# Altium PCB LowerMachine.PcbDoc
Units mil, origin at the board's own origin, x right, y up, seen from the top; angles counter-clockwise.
Board outline 1968.5 x 1968.5 mil, 2 copper layers (Top Layer, Bottom Layer); 45 components, 60 nets, 205 pads, 58 vias.
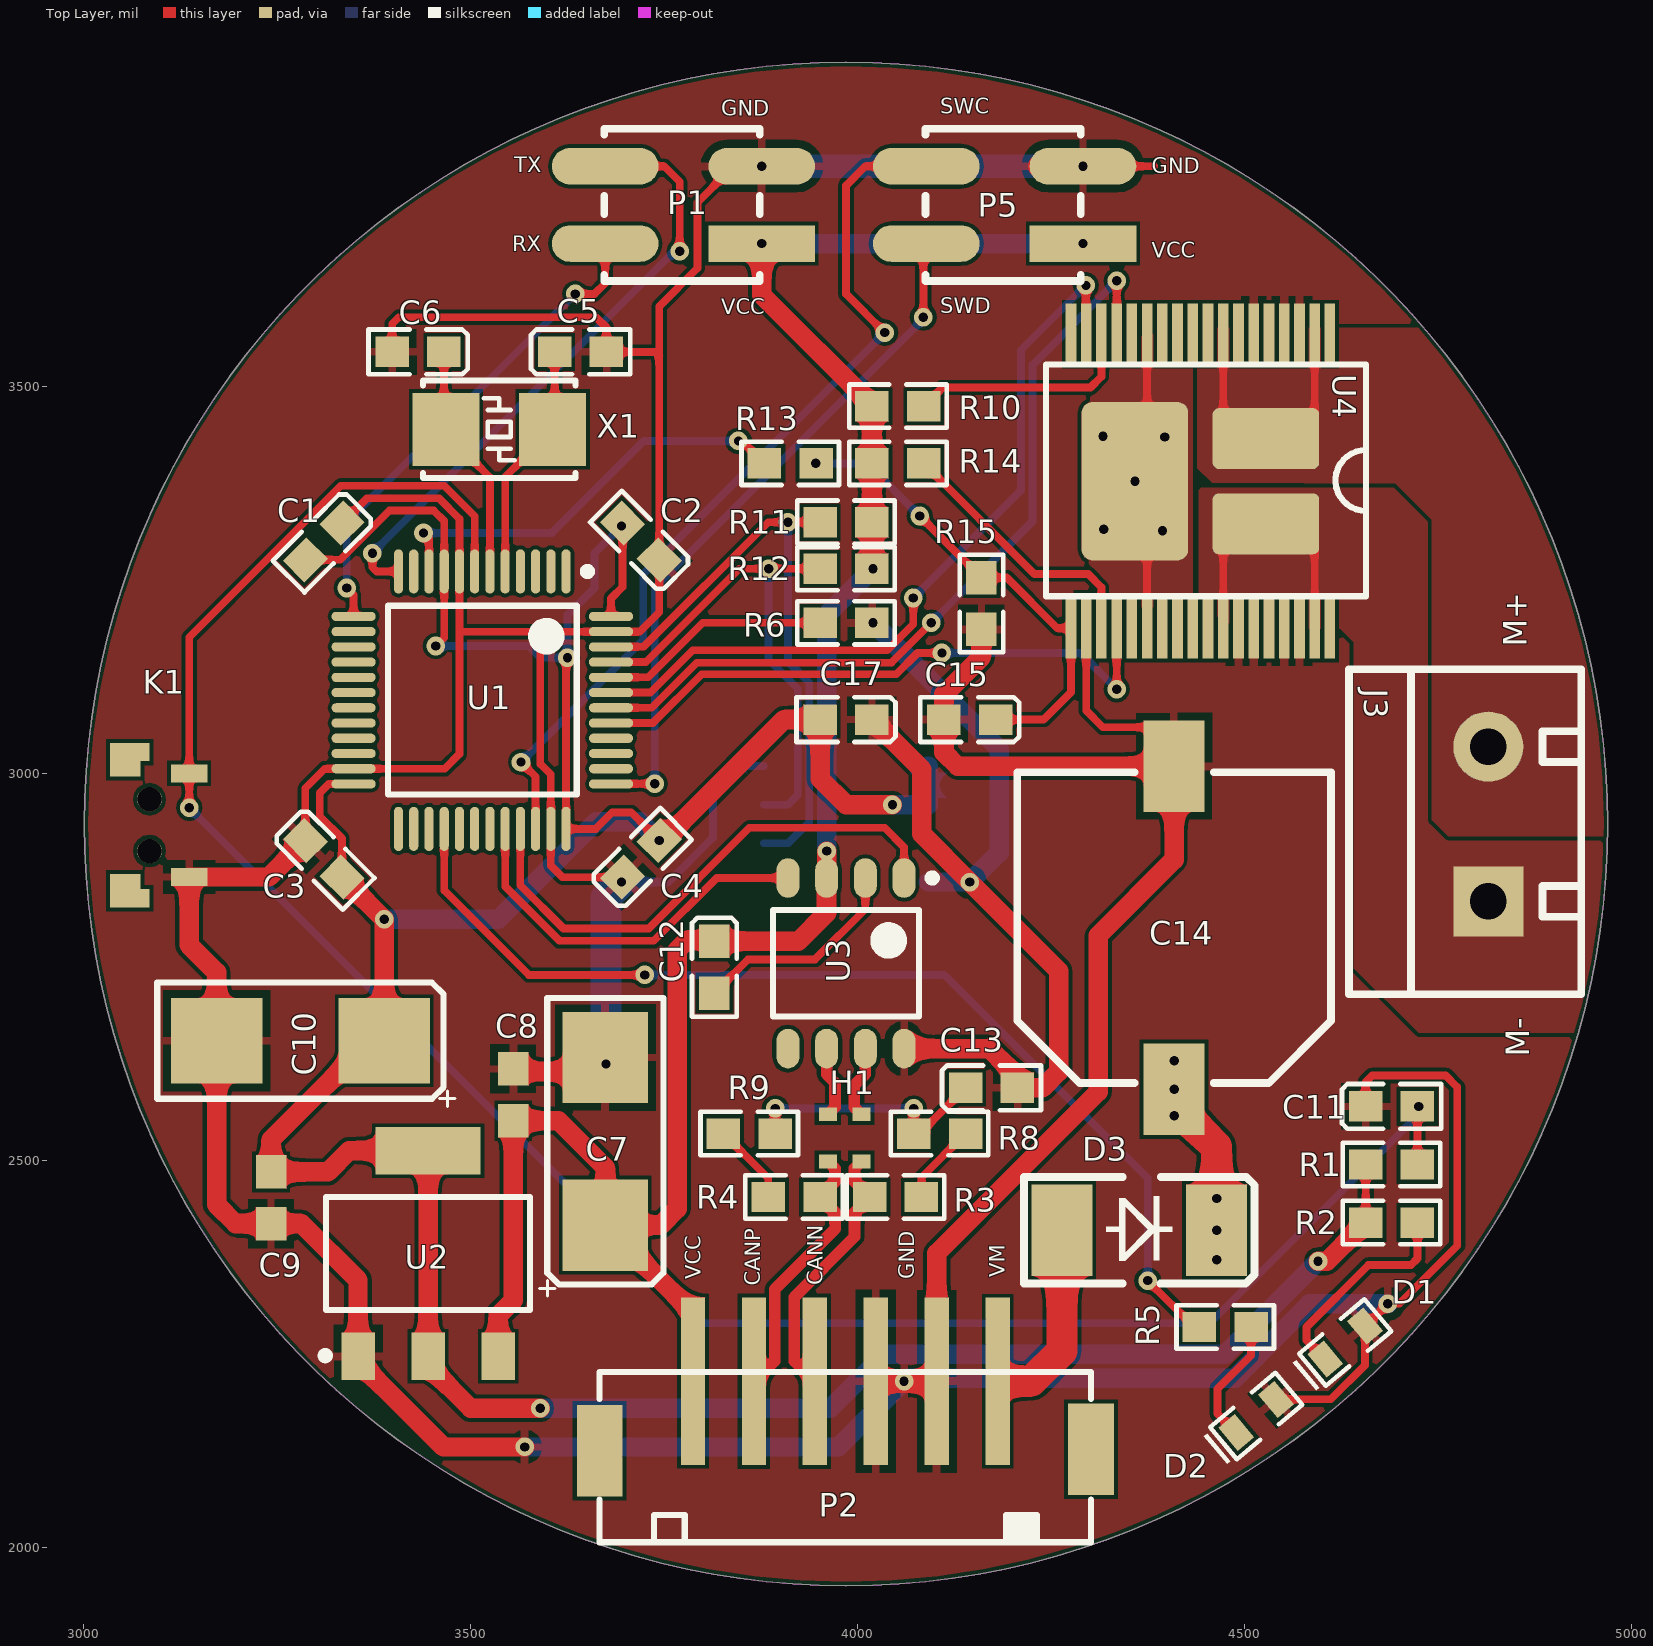
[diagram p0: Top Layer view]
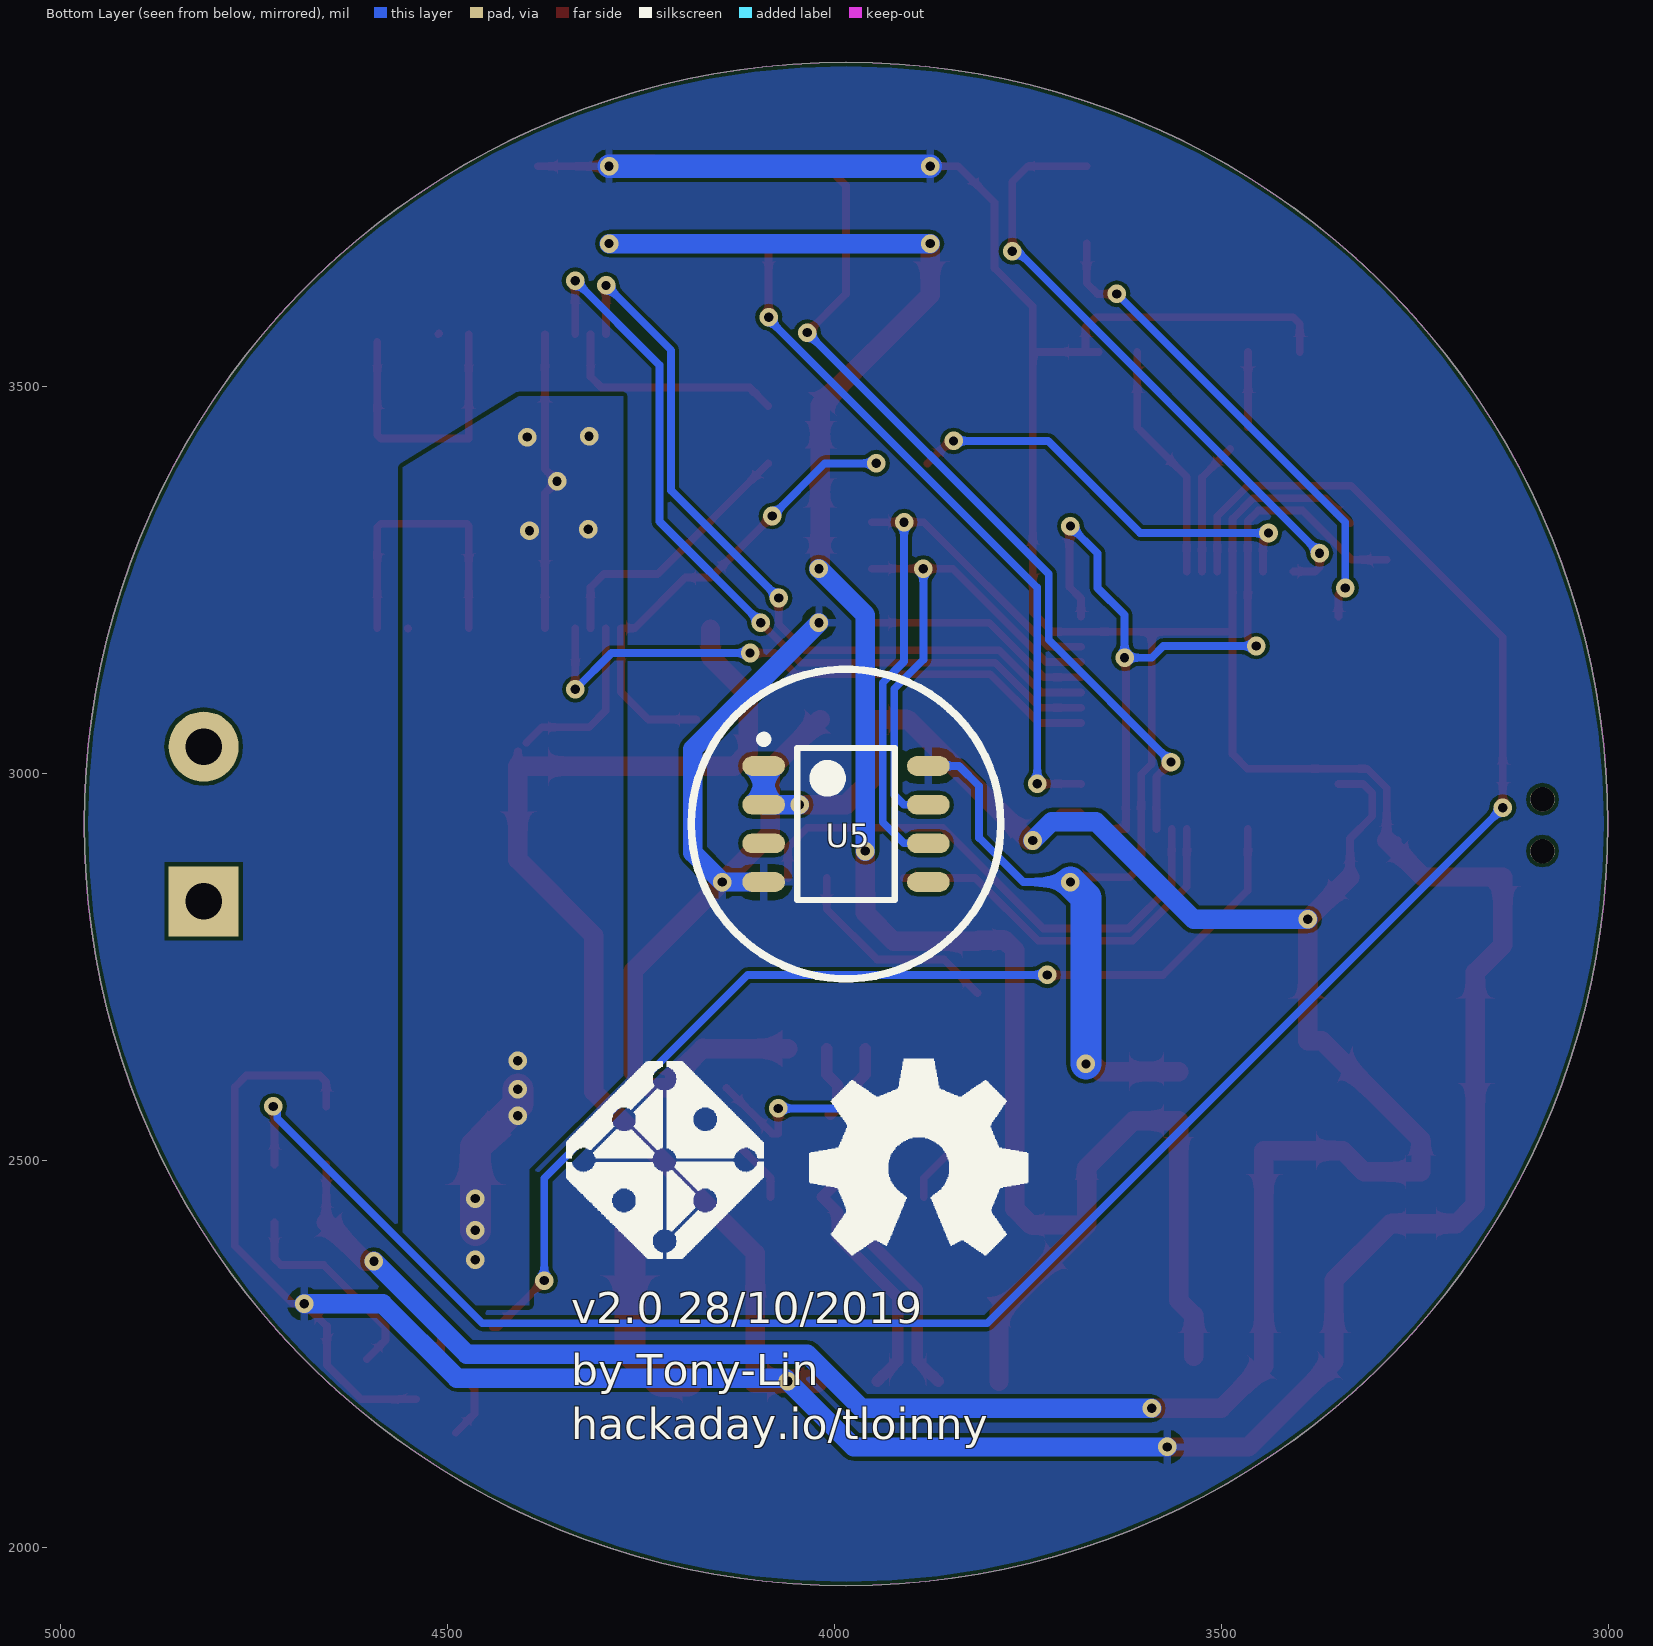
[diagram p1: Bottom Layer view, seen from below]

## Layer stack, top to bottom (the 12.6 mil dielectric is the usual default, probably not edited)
Top Solder: solder mask 0.4, Solder Resist, Dk 3.5
Top Layer: signal copper 1.4
Dielectric 1: dielectric 12.6, FR-4, Dk 4.8
Bottom Layer: signal copper 1.4
Bottom Solder: solder mask 0.4, Solder Resist, Dk 3.5

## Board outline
3000.75,2935 ccw(c3985,2935) 3985,1950.75 ccw(c3985,2935) 4969.25,2935 ccw(c3985,2935) 3985,3919.25 ccw(c3985,2935)

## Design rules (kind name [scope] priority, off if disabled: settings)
Clearance [All] p1: gap=5
DiffPairsRouting [All] p1: maxlimit=10 minlimit=10 mostfreqgap=10 toplayer_minwidth=15 toplayer_maxwidth=15 toplayer_prefwidth=15 bottomlayer_minwidth=15 bottomlayer_maxwidth=15 bottomlayer_prefwidth=15 maxuncoupledlength=500
PolygonConnect PolygonConnect_3 [InNet('24V')] p1: connectstyle=Direct reliefconductorwidth=10 reliefentries=4 polygonreliefangle="90 Angle" airgapwidth=10
PolygonConnect PolygonConnect_2 [InNet('GND')] p2: connectstyle=Relief reliefconductorwidth=10 reliefentries=4 polygonreliefangle="90 Angle" airgapwidth=10
PolygonConnect PolygonConnect_1 [InNet('M+')] p3: connectstyle=Direct reliefconductorwidth=10 reliefentries=4 polygonreliefangle="90 Angle" airgapwidth=10
PolygonConnect [InNet('M-')] p4: connectstyle=Direct reliefconductorwidth=10 reliefentries=4 polygonreliefangle="90 Angle" airgapwidth=10
RoutingVias [All] p1: holewidth=28 width=50 viastyle="Through Hole" minholewidth=28 minwidth=50 maxholewidth=28 maxwidth=50
SolderMaskExpansion [All] p1: expansion=4
Width [All] p1: maxlimit=40 minlimit=6 preferedwidth=10
29 further rules are at their usual default settings.

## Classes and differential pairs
differential pair IN: +IN_P -IN_N
differential pair CAN: +CAN_P -CAN_N

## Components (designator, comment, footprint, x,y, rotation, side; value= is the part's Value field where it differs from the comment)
C1 "104" Cap-0603 3310,3300 r225 top
C2 "104" Cap-0603 3720,3300 r135 top
C3 "104" Cap-0603 3310,2890 r315 top
C4 "104" Cap-0603 3720,2890 r45 top
C5 "22pf" Cap-0603 3642,3545 r0 top
C6 "22pf" Cap-0603 3432,3545 r180 top
C7 "100uf" tan_cap_C 3674,2525 r90 top
C8 "104" Cap-0603-M 3555,2585 r270 top
C9 "104" Cap-0603-M 3242,2452 r90 top
C10 "100uf" tan_cap_C 3280,2655 r180 top
C11 "105" Cap-0603 4690,2570 r0 top
C12 "104" Cap-0603 3815,2750 r270 top
C13 "100nf" Cap-0603 4173,2594 r0 top
C14 "35v 470uf" CAPE_G_10X10.3X10.2 4409,2801 r270 top
C15 "10nf" Cap-0603 4145,3070 r180 top
C17 "100nf" Cap-0603 3985,3070 r180 top
D1 "LED_SMD_BLUE" LED_0603_B 4630,2265 r40 top
D2 "LED_SMD_WHITE" LED_0603_W 4515,2170 r40 top
D3 "1N5824" DO-214AC/SMA 4269,2410 r0 top
H1 "共模扼流圈" 共模扼流圈 4005,2560 r270 top
J3 "Motor interface" KF301-5.0-2P 4815,2835 r90 top
K1 "KEY" SW-SMD-2X4 3085,2900 r90 top
P1 "Header_2X2" Header_SMD_2.54X2 3775,3735 r90 top
P2 "PH2.0-6P" PH2.0S-6P 4181,2215 r180 top
P5 "Header_2X2" Header_SMD_2.54X2 4190,3735 r90 top
R1 "10K" Res-0603 4690,2495 r0 top
R2 "470R" Res-0603 4690,2420 r0 top
R3 "60R" Res-0603 4049,2453 r0 top
R4 "60R" Res-0603 3918,2453 r0 top
R5 "470" Res-0603 4475,2285 r0 top
R6 "10K" Res-0603 3985,3195 r180 top
R8 "0R" Res-0603 4106,2535 r180 top
R9 "0R" Res-0603 3860,2535 r180 top
R10 "4.7K" Res-0603 4052,3475 r180 top
R11 "4.7K" Res-0603 3985,3325 r180 top
R12 "4.7K" Res-0603 3985,3265 r180 top
R13 "10K" Res-0603 3913,3401 r0 top
R14 "4.7K" Res-0603 4052,3401 r0 top
R15 "4.7K" Res-0603 4160,3220 r90 top
U1 "stm32f103c8t6" stm32f103c8t6 3515,3095 r270 top
U2 "AMS1117" AMS1117 3445,2380 r0 top
U3 "tja1050" tja1050 3985,2755 r270 top
U4 "VNH5180A-E" *SSO-36 4443,3378 r270 top
U5 "AS5600" AS5600 3985,2935 r180 bottom
X1 "XTAL-2P" "OSC 5032-2P" 3537,3445 r0 top

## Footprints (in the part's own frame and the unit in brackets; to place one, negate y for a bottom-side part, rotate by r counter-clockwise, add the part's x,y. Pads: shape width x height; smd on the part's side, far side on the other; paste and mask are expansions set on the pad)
*SSO-36 [mm]
  rect 2x0.35 smd: 1(-4.825,4.25) 2(-4.825,3.75) 3(-4.825,3.25) 4(-4.825,2.75) 5(-4.825,2.25) 6(-4.825,1.75) 7(-4.825,1.25) 8(-4.825,0.75) 9(-4.825,0.25) 10(-4.825,-0.25) 11(-4.825,-0.75) 12(-4.825,-1.25) 13(-4.825,-1.75) 14(-4.825,-2.25) 15(-4.825,-2.75) 16(-4.825,-3.25) 17(-4.825,-3.75) 18(-4.825,-4.25) 19(4.825,-4.25) 20(4.825,-3.75) 21(4.825,-3.25) 22(4.825,-2.75) 23(4.825,-2.25) 24(4.825,-1.75) 25(4.825,-1.25) 26(4.825,-0.75) 27(4.825,-0.25) 28(4.825,0.25) 29(4.825,0.75) 30(4.825,1.25) 31(4.825,1.75) 32(4.825,2.25) 33(4.825,2.75) 34(4.825,3.25) 35(4.825,3.75) 36(4.825,4.25)
  rrect20% 2x3.5 smd: 2(-1.4,2.15) 35(1.4,2.15)
  rrect20% 5.2x3.5 smd: 13(0,-2.15)
  silkscreen extent -3.82,-5.07 3.78,5.43, body extent -5.21,-5.15 5.09,5.15, height 2.47
AMS1117 [mm]
  rect 1.1x1.55 smd: 1(-2.3,-3.375) 2(0,-3.375) 3(2.3,-3.375)
  rect 3.45x1.55 smd: 4(0,3.375)
  silkscreen extent -3.5,-3.48 3.35,1.85, body extent -3.25,-3.48 3.25,3.48, height 1.7
AS5600 [mm] "SOIC, 8-Leads, Body 4.90x3.90mm, Pitch 1.27mm, Thermal Pad 0.00x0.00mm, IPC Medium Density"
  oval 1.4x0.65 smd: 1(-2.7,1.905) 2(-2.7,0.635) 3(-2.7,-0.635) 4(-2.7,-1.905) 5(2.7,-1.905) 6(2.7,-0.635) 7(2.7,0.635) 8(2.7,1.905)
  silkscreen extent -2.83,-2.5 1.6,2.9, body extent -2,-2.5 2,2.5, height 1.75
Cap-0603 [mm]
  rect 1.1x1 smd: 1(-0.85,0) 2(0.85,0)
  silkscreen extent -1.63,-0.74 1.63,0.74, body extent -0.8,-0.4 0.8,0.4, height 0.6
Cap-0603-M [mm]
  rect 1.1x1 smd: 1(-0.85,0) 2(0.85,0)
  body extent -0.8,-0.4 0.8,0.4, height 0.6
CAPE_G_10X10.3X10.2 [mm]
  rect 3x2 smd: 1(5.3,0) 2(-5.3,0)
  silkscreen extent -5.1,-5.15 5.1,5.15, body extent -5.8,-5.15 5.8,5.15, height 10.2
DO-214AC/SMA [mm] "塑封二极管"
  rect 2x3 smd: A(-0.127,0) K(4.953,0)
  silkscreen extent -1.37,-1.75 6.2,1.75, body extent 0.11,-1.35 4.71,1.35, height 2.4
Header_SMD_2.54X2 [mm]
  rect 1.2x3.5 smd: 1(-1.27,-2.57)
  oval 1.2x3.5 smd: 2(1.27,-2.57) 3(1.27,2.57) 4(-1.27,2.57)
  silkscreen extent -2.5,-2.5 2.5,2.6, body extent -2.58,-3.75 2.5,3.75, height 9.7
KF301-5.0-2P [mm] "可拼接端子/6A"
  rect 2.3x2.3 hole 1.2: 1(0,0)
  round 2.3 hole 1.2: 2(5.08,0)
  silkscreen extent -3.05,-3.05 7.62,4.57, body extent -3,-3.09 7.5,4.51, height 10.05
LED_0603_B [mm]
  rect 0.7x1 smd: 1(-0.85,0) 2(0.85,0)
  silkscreen extent -1.75,-0.69 1.4,0.69, body extent -0.8,-0.42 0.8,0.38, height 0.61
LED_0603_W [mm]
  rect 0.7x1 smd: 1(-0.85,0) 2(0.85,0)
  silkscreen extent -1.75,-0.69 1.4,0.69, body extent -0.8,-0.42 0.8,0.38, height 0.61
"OSC 5032-2P" [mm]
  rect 2.2x2.4 smd: 1(-1.75,0) 2(1.75,0)
  silkscreen extent -2.5,-1.6 2.5,1.6, body extent -2.5,-1.52 2.5,1.68, height 0.86
PH2.0S-6P [mm]
  rect 1.5x3 smd: 0(-3.064,2.238) 0(13.064,2.286)
  rect 0.8x5.5 smd: 1(0,0) 2(2,0) 3(4,0) 4(6,0) 5(8,0) 6(10,0)
  silkscreen extent -3.06,-0.3 13.06,5.29, body extent -3,-2.5 13,5.3, height 6.15
Res-0603 [mm]
  rect 1.1x1 smd: 1(-0.85,0) 2(0.85,0)
  silkscreen extent -1.6,-0.71 1.6,0.71, body extent -0.8,-0.4 0.8,0.4, height 0.38
stm32f103c8t6 [mm] "QFP, 100-Leads, Body 14.00x20.00mm, Pitch 0.65mm, IPC Medium Density"
  oval 1.45x0.3 smd: 1(-4.225,2.75) 2(-4.225,2.25) 3(-4.225,1.75) 4(-4.225,1.25) 5(-4.225,0.75) 6(-4.225,0.25) 7(-4.225,-0.25) 8(-4.225,-0.75) 9(-4.225,-1.25) 10(-4.225,-1.75) 11(-4.225,-2.25) 12(-4.225,-2.75) 25(4.225,-2.75) 26(4.225,-2.25) 27(4.225,-1.75) 28(4.225,-1.25) 29(4.225,-0.75) 30(4.225,-0.25) 31(4.225,0.25) 32(4.225,0.75) 33(4.225,1.25) 34(4.225,1.75) 35(4.225,2.25) 36(4.225,2.75)
  oval 0.3x1.45 smd: 13(-2.75,-4.225) 14(-2.25,-4.225) 15(-1.75,-4.225) 16(-1.25,-4.225) 17(-0.75,-4.225) 18(-0.25,-4.225) 19(0.25,-4.225) 20(0.75,-4.225) 21(1.25,-4.225) 22(1.75,-4.225) 23(2.25,-4.225) 24(2.75,-4.225) 37(2.75,4.225) 38(2.25,4.225) 39(1.75,4.225) 40(1.25,4.225) 41(0.75,4.225) 42(0.25,4.225) 43(-0.25,4.225) 44(-0.75,4.225) 45(-1.25,4.225) 46(-1.75,4.225) 47(-2.25,4.225) 48(-2.75,4.225)
  silkscreen extent -4.35,-3.1 3.1,3.58, body extent -3.5,-3.5 3.5,3.5, height 1.6
SW-SMD-2X4 [mm]
  rect 0.6x1.3 smd: 0(-1.55,0.65) 0(3.25,0.65)
  rect 0.6x1 smd: 0(-1.05,0.8) 0(2.75,0.8)
  round 0.8 hole 0.8: 0(0,0) 0(1.7,0)
  rect 0.6x1.2 smd: 1(-0.85,-1.3) 3(2.55,-1.3)
  body extent -2.97,-1.8 4.83,1.8, height 3.5
tan_cap_C [mm]
  rect 3x2.8 smd: 1(-2.75,0) 2(2.75,0)
  silkscreen extent -5.08,-1.91 4.7,2.16, body extent -3.15,-1.6 3.15,1.6, height 2.5
tja1050 [mm] "SOP, 8-Leads, Body 4.90x3.90mm, Pitch 1.27mm, IPC Medium Density"
  oval 1.3x0.75 smd: 1(-2.8,1.905) 2(-2.8,0.635) 3(-2.8,-0.635) 4(-2.8,-1.905) 5(2.8,-1.905) 6(2.8,-0.635) 7(2.8,0.635) 8(2.8,1.905)
  silkscreen extent -2.92,-2.4 1.75,2.96, body extent -1.9,-2.4 1.9,2.4, height 1.75
共模扼流圈 [mm]
  rect 0.45x0.6 smd: 1(0,0) 2(0,-1.1) 3(1.55,-1.1) 4(1.55,0)

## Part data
C1 C2 C3 C4 C5 C6 C8 C9 C11 C12 C13: library part CAP
C7 C10: library part tan_cap
C14: library part CAPE-SMD, "贴片电解电容"
C15 C17: library part CAP, "贴片陶瓷电容"
D1 D2: "发光二极管"
D3: library part DIODE, "普通二极管"
J3: library part KF301-2P
R1 R2 R3 R4 R5 R6 R8 R9 R10 R11 R12 R13 R14 R15: library part RES, "贴片电阻"
U4: "Automotive fully integrated H-bridge motor driver"
X1: "2脚无源脚晶振"

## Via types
v1: diameter 24, hole 12, Top Layer to Bottom Layer, 58 vias

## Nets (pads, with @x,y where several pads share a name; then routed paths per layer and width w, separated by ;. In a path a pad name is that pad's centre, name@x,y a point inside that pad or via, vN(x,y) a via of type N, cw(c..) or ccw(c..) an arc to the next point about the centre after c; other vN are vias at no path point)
3.3V: C1.2 C2.2 C3.2 C4.2 C9.2 C10.1 C17.2 R1.1 R2.1 U1.9 U1.24 U1.36 U1.48 U2.2 U2.4 U5.1 U5.2 | length 4760.9
  Top Layer w10: C1.2 3331.34,3276.34 3395,3340 3452.37,3340 3465.79,3326.59 U1.9 3465.79,3175.79 v1(3455,3165) ; C3.2 3333.66,2916.34 3305,2945 3305,2975 3316.73,2986.73 U1.24 ; v1(3625,3150) 3623.27,3148.27 U1.36 3661.66,2928.66 3683,2950 3707.33,2950 v1(3743.66,2913.66) ; U1.48 3681.34,3226.34 3696.34,3241.34 C2.2 ; R2.1 R1.1
  Top Layer w25: C3.2 v1(3388.27,2811.73) C10.1 3370,2655 3242,2527 C9.2 3315.46,2485.46 3342.87,2512.87 U2.4 U2.2 3445,2235 3500,2180 v1(3590,2180) ; v1(3743.66,2913.66) 3748.66,2913.66 3905,3070 C17.2 3951.54,2993.46 3985,2960 v1(4045,2960) ; v1(4595,2370) 4606.54,2370 R2.1
  Bottom Layer w10: v1(3455,3165) 3575,3165 3590,3150 v1(3625,3150) 3625,3205 3660,3240 3660,3285 v1(3695,3320)
  Bottom Layer w25: v1(3388.27,2811.73) 3535.73,2811.73 3662,2938 3719.33,2938 v1(3743.66,2913.66) ; v1(3590,2180) 3965,2180 4035,2250 4475,2250 v1(4595,2370) ; v1(4045,2960) U5.2 U5.1
24V: C14.1 D3.K U4.13 U4.24 | length 598.1
  Top Layer w10: U4.24 4374.1,3362.25 v1(4358.35,3378) 4374.1,3393.75 U4.13@4374.1,3567.96
  Top Layer w40: v1(4409,2592.34) 4409,2573 4464,2518 v1(4464,2410)
  other v1: 4464,2372 4464,2451 4409,2558 4409,2629 4394,3314 4318,3316 4397,3435 4317,3436
ADC: R13.1 U1.10 | length 554.4
  Top Layer w10: v1(3439,3311) 3446.1,3303.9 U1.10 ; v1(3846,3430) 3850.54,3430 R13.1
  Bottom Layer w10: v1(3439,3311) 3605,3311 3724,3430 v1(3846,3430)
BOOT0: R6.2 U1.44 | length 299.4
  Top Layer w10: U1.44 3729.27,3124.53 3799.75,3195 R6.2
BOOT1: U1.20
CAN_N: H1.4 P2.4 R3.1 | length 347.7
  Top Layer w15: P2.4 3937.28,2222.5 3936.5,2222.5 3918,2241 3918,2323.64 3996,2401.64 3996,2433.46 R3.1 3996,2472.54 3996,2489.98 H1.4
CAN_P: H1.3 P2.5 R4.2 | length 348.1
  Top Layer w15: P2.5 3873.54,2222.5 3874.5,2222.5 3893,2241 3893,2334 3971,2412 3971,2433.46 R4.2 3971,2472.54 3971,2489.67 H1.3
CAN_RX: U1.32 U3.4 | length 502.6
  Top Layer w10: U1.32 3544.53,2854.26 3614.79,2784 3736.63,2784 3817.86,2865.24 U3.4
CAN_TX: U1.33 U3.1 | length 695.7
  Top Layer w10: U1.33 3564.21,2855.79 3620,2800 3730,2800 3860,2930 4035,2930 4060,2905 U3.1
GND: C1.1 C2.1 C3.1 C4.1 C5.2 C6.2 C7.2 C8.1 C9.1 C10.2 C11.1 C13.2 C14.2 C15.2 C17.1 D1.2 D2.2 K1.1 P1.2 P2.2 P2.3 P5.2 R6.1 R15.1 U1.8 U1.23 U1.35 U1.47 U2.1 U3.8 U4.3 U4.4 U4.6 U4.20 U4.30 U4.31 U4.33 U4.34 U5.4 U5.8 | length 9862.5
  Top Layer w10: C3.1@3271.92,2913.66 C3.1 3286.34,2981.34 3311.42,3006.42 U1.23 3466.42,3006.42 3485.47,3025.47 U1.8 3485.47,3329.53 3459,3356 3366,3356 C1.1 ; C6.2 3398.54,3581.54 3407,3590 3662,3590 3675.46,3576.54 C5.2 ; 3486.89,3183.58 U1.47 3718.58,3183.58 3743.66,3208.66 C2.1 3743.66,3540 ; 3590,3183.58 3590,3012.63 3603.58,2999.04 U1.35 3603.58,2881.42 3618.66,2866.34 C4.1 ; C5.2@3658.46,3545 3738.66,3545 3743.66,3540 ; v1(3876.18,3785) 3840,3785 3793,3738 3793,3653 3743.66,3603.66 3743.66,3540 ; v1(4291.18,3785) 4383,3785 ; U4.20 4295.36,3081.64 4317,3060 4378,3060 C14.2@4398,3040 ; C14.2@4399,3009.66 C14.2 C14.2@4409,3029 ; U4.6@4511,3568.86 U4.6 ; D2.2 4611.52,2191.52 4655.64,2235.64 D1.2 4656.52,2286.52 v1(4685,2315) 4700,2315 4775,2390 4775,2595 4760,2610 4665,2610 4656.54,2601.54 C11.1 ; U4.33@4551,3187.77 U4.33
  Top Layer w25: C3.1 3239.21,2866.54 K1.1 3136.18,2778.82 3171.73,2743.27 C10.2 3171.73,2443.27 3196.46,2418.54 C9.1 3281.46,2418.54 3354.45,2345.55 U2.1 3354.45,2240.55 3465,2130 v1(3570,2130) ; C8.1@3555,2615 3655.73,2615 C7.2 ; C17.1 4083,3005.46 4083,2922 v1(4145,2860) 4260,2745 4260,2615 4239,2594 C13.2 4206.46,2608.54 4170,2645 4169.76,2644.76 U3.8 ; P2.2 4102.26,2380.26 4311,2589 4311,2791 4409,2889 C14.2 ; R15.1 4160,3151 4111.54,3102.54 C15.2 4111.54,3027.46 4129.34,3009.66 C14.2@4399,3009.66
  Top Layer w30: P2.3 v1(4060,2215) P2.2 ; P5.2@4235,3785 v1(4291.18,3785)
  Bottom Layer w10: v1(3695,2860) 3756,2860 3813,2917 3813,2984 3839,3010 U5.8
  Bottom Layer w25: v1(3570,2130) 3975,2130 v1(4060,2215) 4064,2219 4487.84,2219 4583.84,2315 v1(4685,2315) ; v1(4020,3195) 4183,3032 4183,2898 v1(4145,2860) U5.4
  Bottom Layer w30: v1(3876.18,3785) v1(4291.18,3785)
  Bottom Layer w40: v1(3675,2625) 3675,2840 v1(3695,2860)
IN_N: H1.1 U3.7 | length 94.4
  Top Layer w15: H1.1 3995.85,2569.15 3995.85,2597.52 4010,2611.67 U3.7
IN_P: H1.2 U3.6 | length 93
  Top Layer w15: U3.6 3960,2611.67 3970.85,2600.83 3970.85,2569.15 H1.2
JTCK: P5.4 U1.37 | length 900.1
  Top Layer w10: U1.37 3681.61,2987 v1(3738,2987) ; v1(4085,3590) 4085,3681.18 P5.4
  Bottom Layer w10: v1(3738,2987) 3738,3240.47 4085,3587.47 v1(4085,3590)
JTMS: P5.3 U1.34 | length 1168.7
  Top Layer w10: v1(3565,3015) 3583.9,2996.1 U1.34 ; v1(4035,3570) 3985,3620 3985,3760 4010,3785 P5.3
  Bottom Layer w10: v1(3565,3015) 3723,3173 3723,3258 v1(4035,3570)
M+: J3.2 U4.2 U4.8 | length 375.3
  Top Layer w10: U4.8 4472.53,3433.12 4527.65,3433.12 4586.12,3433.12 4590.64,3437.64 U4.2@4590.64,3558.12
M-: J3.1 U4.29 U4.35 | length 383.8
  Top Layer w10: U4.29 4472.53,3320.53 4474.88,3322.88 4527.65,3322.88 4586.12,3322.88 4590.64,3318.36 U4.35@4590.64,3188.04
NetC12_2: C12.2 U3.2 | length 280.2
  Top Layer w10: C12.2 3858.46,2760 3945,2760 4010,2825 U3.2
NetC13_1: C13.1 R8.2 R9.1 | length 335.3
  Top Layer w10: R9.1 v1(3893.46,2567.46) ; R8.2@4072.46,2535.07 v1(4072.46,2567.46) ; R8.2 4080.54,2535 C13.1
  Bottom Layer w10: v1(3893.46,2567.46) v1(4072.46,2567.46)
NetC15_1: C15.1 R13.2 R15.2 U4.19 | length 612.4
  Top Layer w10: v1(4080.46,3333) R15.2 4192.54,3253.46 4257.96,3188.04 U4.19 4275.68,3105.32 4240.35,3070 C15.1
  Bottom Layer w10: v1(3946,3401) 4012.46,3401 v1(4080.46,3333)
NetD1_1: D1.1 R2.2 | length 278.2
  Top Layer w10: D1.1 4580,2267.86 4580,2285 4660,2365 4715,2365 4723.46,2373.46 R2.2
NetD2_1: D2.1 R5.2 | length 164.6
  Top Layer w10: D2.1 4465,2172.86 4465,2205 4508.46,2248.46 R5.2
NetD3_A: D3.A P2.1 | length 246.2
  Top Layer w40: P2.1@4190,2215 4225,2215 4264,2254 D3.A
NetR3_2: R3.2 R8.1 | length 105.6
  Top Layer w10: R3.2 4082.46,2478 R8.1
NetR4_1: R4.1 R9.2 | length 106
  Top Layer w10: R9.2 3884.54,2477 R4.1
NetR10_1: R10.1 U4.16 | length 300.3
  Top Layer w10: R10.1 4109.46,3499 4301,3499 4315.05,3513.05 U4.16
NetR14_2: R14.2 U4.21 | length 348.8
  Top Layer w10: R14.2 4228.46,3258 4298,3258 4315.05,3240.95 U4.21
NRST: C11.2 K1.3 R1.2 U1.7 | length 2819.2
  Top Layer w10: v1(3136.18,2956.18) K1.3 3136.18,3176.18 3332,3372 3465.63,3372 3505.16,3332.47 U1.7 ; R1.2 C11.2
  Bottom Layer w10: v1(3136.18,2956.18) 3802.36,2290 4455,2290 4720,2555 4720,2565 v1(4725,2570)
OSC8M_IN: C5.1 U1.5 X1.2 | length 303.8
  Top Layer w10: U1.5 3544.53,3383.63 X1.2@3604,3443.1 ; X1.2@3608.54,3447.64 C5.1
OSC8M_OUT: C6.1 U1.6 X1.1 | length 270.6
  Top Layer w10: X1.1@3465.46,3447.64 C6.1 ; X1.1@3488.46,3419.54 3524.84,3383.16 U1.6
OSC32_IN: U1.3
OSC32_OUT: U1.4
PA1: U1.11
PA2: P1.3 U1.12 | length 807.1
  Top Layer w10: v1(3373,3285) 3373,3267 3378.66,3261.34 U1.12 ; P1.3 3750,3785 3770,3765 v1(3770,3675)
  Bottom Layer w10: v1(3373,3285) 3763,3675 v1(3770,3675)
PA3: P1.4 U1.13 | length 638.2
  Top Layer w10: v1(3340,3240) 3348.66,3231.34 U1.13 ; v1(3635,3620) 3660,3620 3673.82,3633.82 P1.4
  Bottom Layer w10: v1(3340,3240) 3340,3325 v1(3635,3620)
PA4: U1.14
PA5: U1.15
PA6: U1.16
PA7: U1.17
PA8: U1.29
PA9: U1.30
PA10: U1.31
PA15: U1.38
PB0: U1.18
PB1: U1.19
PB3: U1.39
PB4: U1.40
PB5: U1.41 U4.22 | length 789.8
  Top Layer w10: U1.41 3735.47,3065.47 3798.5,3128.5 4049.87,3128.5 4077.37,3156 v1(4109,3156) ; U4.22 4334.73,3109.27 v1(4335,3109)
  Bottom Layer w10: v1(4109,3156) 4288,3156 v1(4335,3109)
PB6: U1.42 U4.15 | length 1069.8
  Top Layer w10: U1.42 3733.94,3085.16 3792.29,3143.5 4043.66,3143.5 v1(4095.16,3195) ; U4.15 4335,3568.23 v1(4335,3637)
  Bottom Layer w10: v1(4095.16,3195) 4226,3325.84 4226,3528 v1(4335,3637)
PB7: U1.43 U4.17 | length 1020.7
  Top Layer w10: U1.43 3732.22,3104.84 3786.87,3159.5 4038.45,3159.5 4072,3193.05 v1(4072,3227) ; v1(4295,3631) 4295,3568.32 U4.17
  Bottom Layer w10: v1(4072,3227) 4211,3366 4211,3547 v1(4295,3631)
PB8: R12.2 U1.45 U5.7 | length 677.2
  Top Layer w10: U1.45 3726.33,3144.21 3847.12,3265 v1(3885,3265) R12.2
  Bottom Layer w10: U5.7 3910,2960 3922.5,2972.5 3922.5,3109.87 3885,3147.37 v1(3885,3265)
PB9: R11.2 U1.46 U5.6 | length 806
  Top Layer w10: U1.46 3723.39,3163.9 3884.49,3325 v1(3910,3325) R11.2
  Bottom Layer w10: U5.6 3910,2910 3937.5,2937.5 3937.5,3117.5 3910,3145 v1(3910,3325)
PB10: U1.21
PB11: U1.22
PB12: U1.25
PB13: U1.26
PB14: U1.27
PB15: R5.1 U1.28 | length 1366.2
  Top Layer w10: U1.28 3465.79,2849.21 3575,2740 v1(3725,2740) ; v1(4375,2345) 4435,2285 R5.1
  Bottom Layer w10: v1(3725,2740) 4112,2740 4375,2477 v1(4375,2345)
PC13: U1.2
VBAT: U1.1
VCC: C7.1 C8.2 C12.1 P1.1 P2.6 P5.1 R10.2 R11.1 R12.1 R14.1 U2.3 U3.3 | length 2793.2
  Top Layer w25: U2.3 3535.55,2300 3555,2319.45 C8.2 3613.46,2551.54 3674,2491 C7.1 ; P2.6 3787.3,2303.43 C7.1 ; v1(3876.18,3685) 3876.18,3618.59 4018.46,3476.3 R11.1 R12.1 ; v1(3960,2900) U3.3 3960,2820 3923.5,2783.5 C12.1 C12.1 3813.46,2785 3780,2785 3767,2772 3767,2438 3745.73,2416.73 C7.1
  Bottom Layer w25: v1(3876.18,3685) v1(4291.18,3685) ; v1(3960,2900) 3960,3205 v1(4020,3265)
pads on no net: K1.0 P2.0 U3.5 U4.1 U4.5 U4.7 U4.9 U4.10 U4.11 U4.12 U4.14 U4.18 U4.23 U4.25 U4.26 U4.27 U4.28 U4.32 U4.36 U5.3 U5.5

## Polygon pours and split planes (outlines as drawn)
24V on Top Layer "Top Layer-No Net" (solid, remove dead copper, pour order 12): 4252,3568 4252,3215 4423,3215 4433,3225 4433,3567.96
M+ on Top Layer "Top Layer-No Net" (solid, remove dead copper, pour order 0): 4458.21,3375.79 4439,3395 4439,3576 4800,3576 4967,3409 4986,3390 4986,2919 4763,2919 4745,2937 4742,2940 4742,3082 4742,3328 4695.09,3374.91
M- on Top Layer "Top Layer-No Net" (solid, remove dead copper, pour order 2): 4441,3370.03 4441,3227 4481,3187 4624,3187 4630,3181 4641,3170 4641,2748 4642,2748 4724,2666 4725,2665 4997,2665 4997,3368 4998.03,3369.03
GND on Top Layer "Top Layer-No Net" (solid, remove dead copper, pour order 8): 2643,4297 2895,4045 2895,1451 5353,1451 5501,1303 5803,1605 5803,4358
24V on Bottom Layer "Top Layer-No Net" (solid, remove dead copper, pour order 6): 4273,3488 4273,2610 4394,2489 4394,2313 4558.02,2313 4558.02,3396 4408,3488
GND on Bottom Layer "Top Layer-No Net" (solid, remove dead copper, pour order 10): 2801,4000 2801,1958 2870,1889 2964,1795 5328,1795 5328,3968 5271,4025

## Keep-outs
Keep-Out Layer:
  circle w0.5: c3985,2935 r984.25

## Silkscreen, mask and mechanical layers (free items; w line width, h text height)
Top Overlay:
  lines w5: 3392.95,3217.05 3392.95,3217.05 ; 3637.05,2972.95 3637.05,2972.95
  text "SWC" at 4107,3853 h20
  text "GND" at 3824,3850 h20
  text "TX" at 3556,3777 h20
  text "GND" at 4380,3776 h20
  text "RX" at 3554,3675 h20
  text "VCC" at 4380,3667 h20
  text "SWD" at 4107,3595 h20
  text "VCC" at 3824,3594 h20
  text "M+" at 4865,3164 h30 r90
  text "M-" at 4868,2634 h30 r90
  text "VM" at 4190,2349 h20 r90
  text "VCC" at 3797,2347 h20 r90
  text "GND" at 4073,2347 h20 r90
  text "CANN" at 3955,2339 h20 r90
  text "CANP" at 3874,2338 h20 r90
Bottom Overlay:
  drawing of 1280 lines, arcs and shapes, not listed
  text "v2.0 28/10/2019" at 4340,2290 h40
  text "by Tony-Lin" at 4340,2210 h40
  text "hackaday.io/tloinny" at 4340,2140 h40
